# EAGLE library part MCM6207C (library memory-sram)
MEMORY
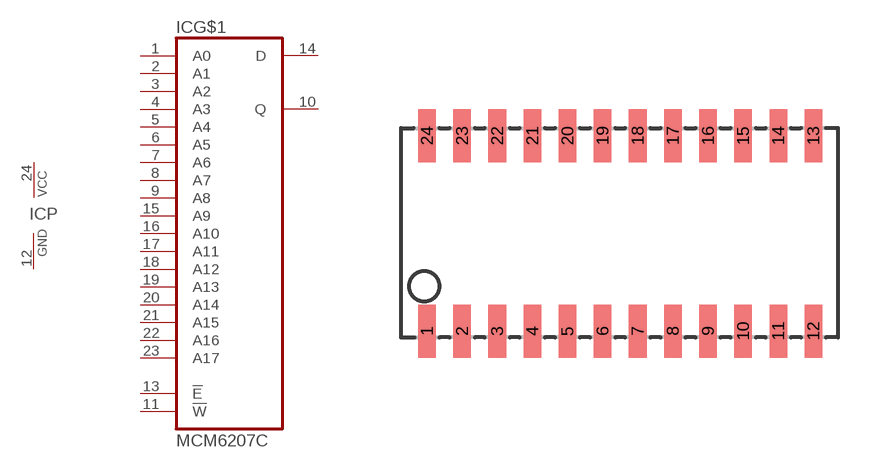
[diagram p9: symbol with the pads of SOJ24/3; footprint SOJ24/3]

Designator prefix IC; gates G$1=CM6207C P=PWRN

## MCM6207C  [SOJ24/3]
1  G$1:A0  in
2  G$1:A1  in
3  G$1:A2  in
4  G$1:A3  in
5  G$1:A4  in
6  G$1:A5  in
7  G$1:A6  in
8  G$1:A7  in
9  G$1:A8  in
10  G$1:Q  hiz
11  G$1:!W  in
12  P:GND  pwr
13  G$1:!E  in
14  G$1:D  in
15  G$1:A9  in
16  G$1:A10  in
17  G$1:A11  in
18  G$1:A12  in
19  G$1:A13  in
20  G$1:A14  in
21  G$1:A15  in
22  G$1:A16  in
23  G$1:A17  in
24  P:VCC  pwr

## Footprint SOJ24/3 (pad centres in mm)
Small Outline J-Bend
smd 0.635 x 1.905: 1 -6.35,-3.531; 2 -5.08,-3.531; 3 -3.81,-3.531; 4 -2.54,-3.531; 5 -1.27,-3.531; 6 0,-3.531; 7 1.27,-3.531; 8 2.54,-3.531; 9 3.81,-3.531; 10 5.08,-3.531; 11 6.35,-3.531; 12 7.62,-3.531; 13 7.62,3.531; 14 6.35,3.531; 15 5.08,3.531; 16 3.81,3.531; 17 2.54,3.531; 18 1.27,3.531; 19 0,3.531; 20 -1.27,3.531; 21 -2.54,3.531; 22 -3.81,3.531; 23 -5.08,3.531; 24 -6.35,3.531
